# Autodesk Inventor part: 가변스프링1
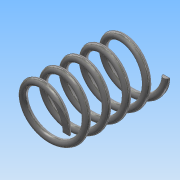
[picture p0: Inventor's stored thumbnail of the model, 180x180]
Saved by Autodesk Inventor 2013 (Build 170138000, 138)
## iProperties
Created: 2018-10
Part Number: 가변스프링1
Material: 스테인리스강
Document SubType Name: Modeling
Designer: Administrator
Density: 8.08 g/cm^3
Mass: 6.29082 g
Surface Area: 15.794 cm^2
Volume: 0.778567 cm^3
Author: Administrator
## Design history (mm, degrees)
sketch "스케치1"
  geometry: L1 (0, 0)-(0, 30.471); L2 (0, 30.471)-(8, 30.471); L3 (0, 0)-(8, 0); C1 r 1 at (8, 0)
  constraints: 6 end point, 1 centre point, 1 horizontal alignment, 1 parallel, 1 perpendicular, 1 vertical
  dimensions: "d0" = 30.47091 distance of L1.start L1.end (derived); "d1" = 8 distance of L1.end L2.end; "d2" = 2 diameter of C1; "d3" = 16 diameter of L3.end L1
feature "코일1" sketch "스케치1" pitch "d4" = 10; turns "d6" = 5; dims "d5" = 30.47091 (= d0), "d7" = 0, angle "d8" = 90 deg, angle "d9" = 90 deg, "d10" = 0, "d11" = 0
sketch "스케치2"
  geometry: L1 (30.471, 10)-(0, 10); L2 (0, 10)-(0, -10); L3 (0, -10)-(30.471, -10); L4 (30.471, -10)-(30.471, 10); 2 further points
  constraints: 8 end point, 2 parallel, 1 coincident, 1 horizontal, 1 midpoint, 1 perpendicular
  dimensions: "d12" = 30.47091 distance of L3.end L2.end (derived); "d13" = 20 distance of L2.end L1.end
extrude "돌출1" sketch "스케치2" stored distance "d14" = 0; taper "d15" = 0 deg
node "솔리드1"
